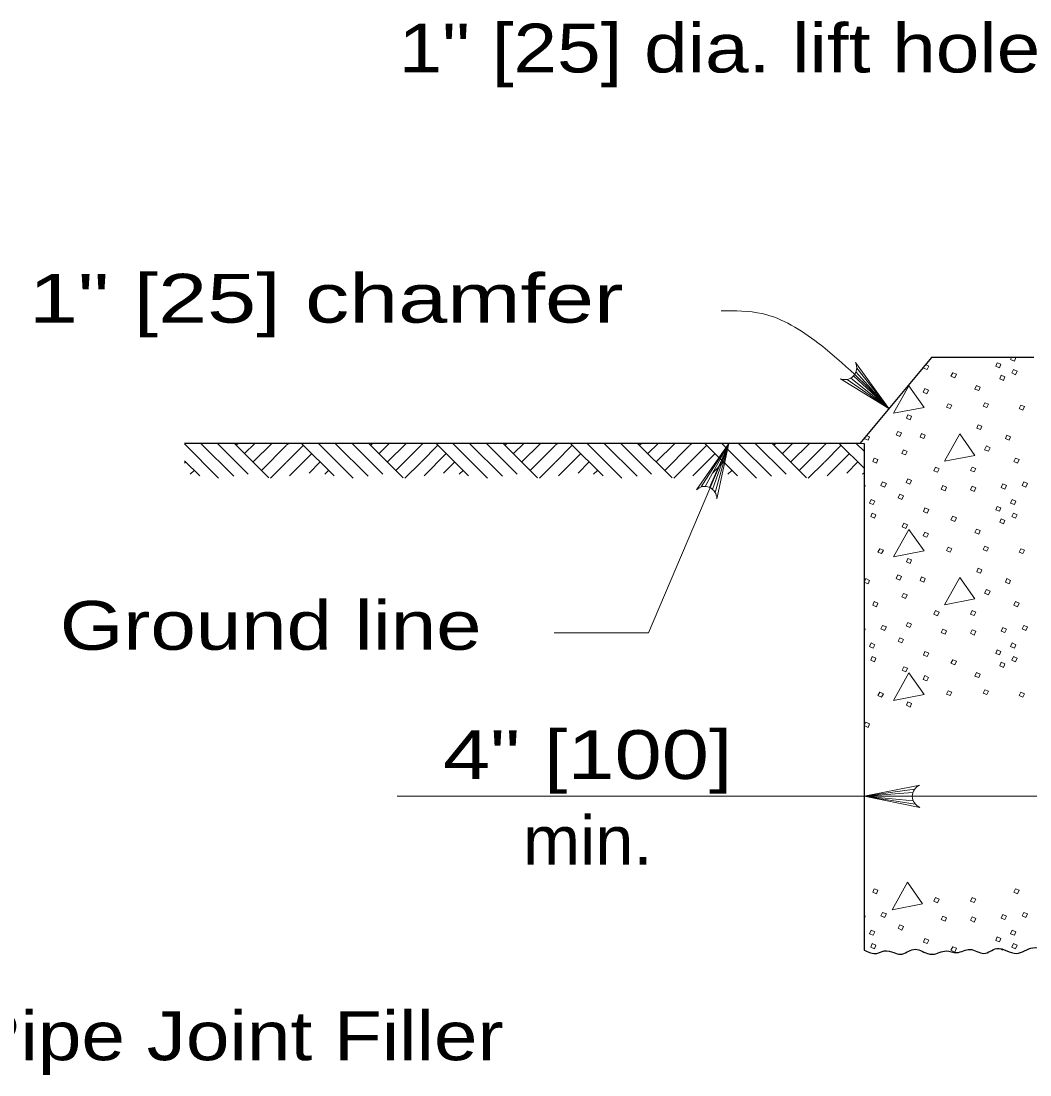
# Model space of a CAD drawing. Extents: x 1083.1 to 1117.1, y 719.4 to 741.4.
# Drawn here: x 1096.956 to 1100.181, y 731.674 to 735.044 of the extents above; entities that cross this region are included whole.
import ezdxf
from ezdxf.enums import TextEntityAlignment as Align

# ---------------------------------------------------------------- set-up
doc = ezdxf.new("R2010")
doc.units = 0
doc.header["$LTSCALE"] = 0.062
doc.layers.add('1', color=7, linetype='Continuous', lineweight=13)

msp = doc.modelspace()

# ---------------------------------------------------------------- linework, layer by layer
at = {"layer": '1'}
for p, q in [((1099.62458, 733.92192), (1099.72992, 733.80475)), ((1099.62717, 733.93383), (1099.72992, 733.80475)), ((1099.59625, 733.89767), (1099.72992, 733.80475)), ((1099.60792, 733.90217), (1099.72992, 733.80475)), ((1099.61683, 733.90933), (1099.72992, 733.80475)), ((1097.4785, 733.69167), (1097.5875, 733.58267)), ((1097.53033, 733.6935), (1097.63575, 733.58808)), ((1097.58408, 733.6935), (1097.68233, 733.59533)), ((1097.63775, 733.6935), (1097.74775, 733.58358)), ((1097.64367, 733.68758), (1097.64967, 733.6935)), ((1097.6705, 733.66075), (1097.70325, 733.6935)), ((1097.69742, 733.63392), (1097.757, 733.6935)), ((1097.72425, 733.60708), (1097.80375, 733.68658)), ((1097.80483, 733.68767), (1097.81067, 733.6935)), ((1097.80483, 733.63383), (1097.8585, 733.68758)), ((1097.85258, 733.6935), (1097.95675, 733.58942)), ((1097.90633, 733.6935), (1098.01717, 733.58267)), ((1097.96, 733.6935), (1098.0655, 733.58808)), ((1098.01375, 733.6935), (1098.11208, 733.59533)), ((1098.06742, 733.6935), (1098.1775, 733.58358)), ((1098.07342, 733.68758), (1098.07942, 733.6935)), ((1098.10025, 733.66075), (1098.133, 733.6935)), ((1098.12708, 733.63392), (1098.18675, 733.6935)), ((1098.15392, 733.60708), (1098.23342, 733.68658)), ((1098.23458, 733.68767), (1098.24042, 733.6935)), ((1098.23458, 733.63383), (1098.28825, 733.68758)), ((1098.28233, 733.6935), (1098.3865, 733.58942)), ((1098.336, 733.6935), (1098.44692, 733.58267)), ((1098.38967, 733.6935), (1098.49517, 733.58808)), ((1098.44342, 733.6935), (1098.54175, 733.59533)), ((1098.49717, 733.6935), (1098.60717, 733.58358)), ((1098.50308, 733.68758), (1098.50908, 733.6935)), ((1098.52992, 733.66075), (1098.56267, 733.6935)), ((1098.55675, 733.63392), (1098.61642, 733.6935)), ((1098.58367, 733.60708), (1098.66308, 733.68658)), ((1098.66425, 733.68767), (1098.67008, 733.6935)), ((1098.66425, 733.63383), (1098.71792, 733.68758)), ((1098.712, 733.6935), (1098.81617, 733.58942)), ((1098.76567, 733.6935), (1098.87658, 733.58267)), ((1098.81942, 733.6935), (1098.92492, 733.58808)), ((1098.87317, 733.6935), (1098.97142, 733.59533)), ((1098.92683, 733.6935), (1099.03692, 733.58358)), ((1098.93275, 733.68758), (1098.93875, 733.6935)), ((1098.95967, 733.66075), (1098.99242, 733.6935)), ((1098.9865, 733.63392), (1099.04608, 733.6935)), ((1099.01333, 733.60708), (1099.09283, 733.68658)), ((1099.09392, 733.68767), (1099.09975, 733.6935)), ((1099.09392, 733.63383), (1099.14767, 733.68758)), ((1099.13025, 733.55425), (1099.21867, 733.6935)), ((1099.14167, 733.6935), (1099.24583, 733.58942)), ((1099.14233, 733.55567), (1099.21867, 733.6935)), ((1099.15675, 733.5525), (1099.21867, 733.6935)), ((1099.16642, 733.54633), (1099.21867, 733.6935)), ((1099.17442, 733.53683), (1099.21867, 733.6935)), ((1099.19542, 733.6935), (1099.30625, 733.58267)), ((1099.24908, 733.6935), (1099.35467, 733.58808)), ((1099.30292, 733.6935), (1099.40117, 733.59533)), ((1099.35658, 733.6935), (1099.46658, 733.58358)), ((1099.3625, 733.68758), (1099.3685, 733.6935)), ((1099.38933, 733.66075), (1099.42208, 733.6935)), ((1099.41617, 733.63392), (1099.47583, 733.6935)), ((1099.443, 733.60708), (1099.5225, 733.68658)), ((1099.52367, 733.68767), (1099.5295, 733.6935)), ((1099.52367, 733.63383), (1099.57742, 733.68758)), ((1099.57142, 733.6935), (1099.65058, 733.61442)), ((1099.62508, 733.6935), (1099.65058, 733.66808)), ((1099.65058, 733.6935), (1099.63708, 733.6935)), ((1097.81425, 733.58967), (1097.88542, 733.66075)), ((1098.244, 733.58967), (1098.31508, 733.66075)), ((1098.67367, 733.58967), (1098.74475, 733.66075)), ((1099.21133, 733.67675), (1098.96125, 733.0875)), ((1099.10342, 733.58967), (1099.1745, 733.66075)), ((1099.53308, 733.58967), (1099.60417, 733.66075)), ((1097.4785, 733.638), (1097.52708, 733.58942)), ((1097.4785, 733.62992), (1097.4825, 733.63392)), ((1097.75333, 733.58233), (1097.80375, 733.63275)), ((1097.87692, 733.5985), (1097.91225, 733.63392)), ((1098.183, 733.58233), (1098.23342, 733.63275)), ((1098.30658, 733.5985), (1098.34192, 733.63392)), ((1098.61275, 733.58233), (1098.66308, 733.63275)), ((1098.73625, 733.5985), (1098.77167, 733.63392)), ((1099.0425, 733.58233), (1099.09283, 733.63275)), ((1099.166, 733.5985), (1099.20133, 733.63392)), ((1099.47217, 733.58233), (1099.5225, 733.63275)), ((1099.59567, 733.5985), (1099.631, 733.63392)), ((1097.49675, 733.5945), (1097.50942, 733.60708)), ((1097.9265, 733.5945), (1097.93908, 733.60708)), ((1098.35617, 733.5945), (1098.36875, 733.60708)), ((1098.78592, 733.5945), (1098.7985, 733.60708)), ((1099.21558, 733.5945), (1099.22817, 733.60708)), ((1099.64525, 733.5945), (1099.65058, 733.59975)), ((1098.65942, 733.0875), (1098.96125, 733.0875)), ((1099.81175, 732.58775), (1099.65058, 732.56517)), ((1099.80633, 732.57658), (1099.65058, 732.56517)), ((1098.15858, 732.56517), (1100.59642, 732.56517)), ((1099.80467, 732.56517), (1099.65058, 732.56517)), ((1099.8075, 732.55067), (1099.65058, 732.56517)), ((1099.81367, 732.54025), (1099.65058, 732.56517)), ((1100.0885, 732.07467), (1100.08892, 732.07575)), ((1100.08892, 732.07575), (1100.09458, 732.07317))]:
    msp.add_line(p, q, dxfattribs=at)
at = {"layer": '1', "lineweight": 25}
for p, q in [((1099.63708, 733.6935), (1097.4785, 733.6935)), ((1099.65058, 733.6935), (1099.65058, 732.07317))]:
    msp.add_line(p, q, dxfattribs=at)
msp.add_lwpolyline([(1100.19267, 733.96767), (1099.86592, 733.96767), (1099.63708, 733.6935)], dxfattribs=at)
at = {"layer": '1'}
for points in [[(1100.13533, 733.96767), (1100.13567, 733.9675), (1100.13092, 733.95642), (1100.119, 733.96117), (1100.12167, 733.96767)], [(1099.62342, 733.95175), (1099.72992, 733.80475), (1099.57508, 733.89958)], [(1099.84717, 733.94525), (1099.85708, 733.94058), (1099.85233, 733.9295), (1099.8405, 733.93433), (1099.84275, 733.94)], [(1099.65825, 733.71883), (1099.668, 733.71433), (1099.66325, 733.70325), (1099.65133, 733.70883), (1099.65292, 733.7125)], [(1099.1145, 733.54483), (1099.21867, 733.6935), (1099.17967, 733.51625)], [(1099.65058, 733.56025), (1099.6545, 733.5585), (1099.65058, 733.54917)], [(1099.65058, 733.10142), (1099.6545, 733.09958), (1099.65058, 733.09033)], [(1099.82858, 732.52958), (1099.65058, 732.56517), (1099.82858, 732.60075)], [(1099.65058, 732.18358), (1099.6545, 732.18175), (1099.65058, 732.1725)]]:
    msp.add_lwpolyline(points, dxfattribs=at)
for points in [[(1100.07625, 733.95092), (1100.08817, 733.94617), (1100.08342, 733.93508), (1100.0715, 733.93983)], [(1100.12775, 733.9295), (1100.13958, 733.924), (1100.13483, 733.91292), (1100.123, 733.9185)], [(1099.93383, 733.91925), (1099.94575, 733.9145), (1099.94017, 733.90267), (1099.92833, 733.90817)], [(1100.08892, 733.91133), (1100.10083, 733.90583), (1100.09608, 733.89475), (1100.08417, 733.90025)], [(1099.79383, 733.87733), (1099.74475, 733.7895), (1099.84208, 733.8085)], [(1099.84442, 733.86858), (1099.85633, 733.86308), (1099.85075, 733.852), (1099.83892, 733.85675)], [(1100.00983, 733.87808), (1100.02167, 733.87333), (1100.01692, 733.86225), (1100.00508, 733.867)], [(1099.91883, 733.82033), (1099.93067, 733.81558), (1099.92592, 733.8045), (1099.91408, 733.80925)], [(1100.03675, 733.8235), (1100.04858, 733.81875), (1100.04308, 733.80767), (1100.03117, 733.81242)], [(1100.1515, 733.81558), (1100.16333, 733.81083), (1100.15775, 733.79975), (1100.14592, 733.8045)], [(1099.79067, 733.78475), (1099.8025, 733.78), (1099.79775, 733.76817), (1099.78592, 733.77367)], [(1100.01533, 733.75308), (1100.02725, 733.74833), (1100.0225, 733.73725), (1100.01058, 733.742)], [(1099.75817, 733.73175), (1099.77008, 733.727), (1099.76533, 733.71508), (1099.75342, 733.72067)], [(1099.83417, 733.72542), (1099.846, 733.71983), (1099.84125, 733.70883), (1099.82942, 733.7135)], [(1099.95683, 733.72383), (1099.90775, 733.636), (1100.00508, 733.655)], [(1100.10717, 733.71983), (1100.119, 733.71433), (1100.11425, 733.70325), (1100.10242, 733.70883)], [(1100.0415, 733.68508), (1100.05333, 733.6795), (1100.04783, 733.66842), (1100.03592, 733.67317)], [(1099.77642, 733.67242), (1099.78825, 733.66767), (1099.78275, 733.65658), (1099.77083, 733.66133)], [(1099.683, 733.64625), (1099.69492, 733.64158), (1099.69017, 733.62967), (1099.67825, 733.63525)], [(1099.8785, 733.61783), (1099.89033, 733.61225), (1099.88558, 733.60117), (1099.87375, 733.60592)], [(1099.99633, 733.61783), (1100.00825, 733.61308), (1100.00267, 733.602), (1099.99083, 733.60675)], [(1100.13408, 733.64625), (1100.14592, 733.64158), (1100.14117, 733.62967), (1100.12933, 733.63525)], [(1099.70992, 733.57033), (1099.72175, 733.56558), (1099.71625, 733.55375), (1099.70442, 733.55925)], [(1099.79067, 733.57983), (1099.8025, 733.57425), (1099.79692, 733.56325), (1099.78508, 733.56875)], [(1099.90217, 733.5585), (1099.91408, 733.55292), (1099.90933, 733.54183), (1099.89742, 733.54742)], [(1099.99633, 733.55608), (1100.00825, 733.55133), (1100.00267, 733.5395), (1099.99083, 733.545)], [(1100.09367, 733.564), (1100.10558, 733.5585), (1100.10083, 733.54742), (1100.08892, 733.55217)], [(1100.16092, 733.57033), (1100.17283, 733.56558), (1100.16725, 733.55375), (1100.15542, 733.55925)], [(1099.7645, 733.53075), (1099.77642, 733.52525), (1099.77167, 733.51417), (1099.75975, 733.51967)], [(1099.67275, 733.51417), (1099.68458, 733.50858), (1099.67983, 733.49758), (1099.668, 733.50225)], [(1099.84525, 733.48725), (1099.85708, 733.48175), (1099.85233, 733.47067), (1099.8405, 733.47542)], [(1100.07625, 733.492), (1100.08817, 733.48725), (1100.08342, 733.47617), (1100.0715, 733.48092)], [(1100.12375, 733.51417), (1100.13567, 733.50858), (1100.13092, 733.49758), (1100.119, 733.50225)], [(1099.67667, 733.47067), (1099.68858, 733.46508), (1099.68383, 733.454), (1099.67192, 733.45958)], [(1099.93383, 733.46033), (1099.94575, 733.45558), (1099.94017, 733.44375), (1099.92833, 733.44925)], [(1100.08892, 733.45242), (1100.10083, 733.44692), (1100.09608, 733.43583), (1100.08417, 733.44133)], [(1100.12775, 733.47067), (1100.13958, 733.46508), (1100.13483, 733.454), (1100.123, 733.45958)], [(1099.79383, 733.41842), (1099.74475, 733.33058), (1099.84208, 733.34958)], [(1099.77717, 733.43817), (1099.78908, 733.43342), (1099.78433, 733.42158), (1099.77242, 733.42708)], [(1100.00983, 733.41925), (1100.02167, 733.4145), (1100.01692, 733.40342), (1100.00508, 733.40817)], [(1099.84442, 733.40975), (1099.85633, 733.40417), (1099.85075, 733.39308), (1099.83892, 733.39783)], [(1099.70042, 733.35667), (1099.71225, 733.35192), (1099.70675, 733.34092), (1099.69492, 733.34567)], [(1099.91883, 733.36142), (1099.93067, 733.35667), (1099.92592, 733.34567), (1099.91408, 733.35042)], [(1100.03675, 733.36458), (1100.04858, 733.35983), (1100.04308, 733.34883), (1100.03117, 733.35358)], [(1100.1515, 733.35667), (1100.16333, 733.35192), (1100.15775, 733.34092), (1100.14592, 733.34567)], [(1099.79067, 733.32583), (1099.8025, 733.32108), (1099.79775, 733.30925), (1099.78592, 733.31475)], [(1100.01533, 733.29417), (1100.02725, 733.28942), (1100.0225, 733.27833), (1100.01058, 733.28308)], [(1099.65608, 733.261), (1099.668, 733.25542), (1099.66325, 733.24433), (1099.65133, 733.24992)], [(1099.75817, 733.27283), (1099.77008, 733.26808), (1099.76533, 733.25625), (1099.75342, 733.26175)], [(1099.83417, 733.2665), (1099.846, 733.261), (1099.84125, 733.24992), (1099.82942, 733.25467)], [(1099.95683, 733.26492), (1099.90775, 733.17708), (1100.00508, 733.19608)], [(1100.10717, 733.261), (1100.119, 733.25542), (1100.11425, 733.24433), (1100.10242, 733.24992)], [(1099.77642, 733.2135), (1099.78825, 733.20875), (1099.78275, 733.19767), (1099.77083, 733.20242)], [(1100.0415, 733.22617), (1100.05333, 733.22058), (1100.04783, 733.2095), (1100.03592, 733.21425)], [(1099.683, 733.18742), (1099.69492, 733.18267), (1099.69017, 733.17075), (1099.67825, 733.17633)], [(1100.13408, 733.18742), (1100.14592, 733.18267), (1100.14117, 733.17075), (1100.12933, 733.17633)], [(1099.8785, 733.15892), (1099.89033, 733.15333), (1099.88558, 733.14225), (1099.87375, 733.147)], [(1099.99633, 733.15892), (1100.00825, 733.15417), (1100.00267, 733.14308), (1099.99083, 733.14783)], [(1099.79067, 733.12092), (1099.8025, 733.11542), (1099.79692, 733.10433), (1099.78508, 733.10983)], [(1099.70992, 733.11142), (1099.72175, 733.10667), (1099.71625, 733.09483), (1099.70442, 733.10033)], [(1099.90217, 733.09958), (1099.91408, 733.094), (1099.90933, 733.08292), (1099.89742, 733.0885)], [(1099.99633, 733.09717), (1100.00825, 733.09242), (1100.00267, 733.08058), (1099.99083, 733.08608)], [(1100.09367, 733.10508), (1100.10558, 733.09958), (1100.10083, 733.0885), (1100.08892, 733.09325)], [(1100.16092, 733.11142), (1100.17283, 733.10667), (1100.16725, 733.09483), (1100.15542, 733.10033)], [(1099.67275, 733.05525), (1099.68458, 733.04975), (1099.67983, 733.03867), (1099.668, 733.04342)], [(1099.7645, 733.07183), (1099.77642, 733.06633), (1099.77167, 733.05525), (1099.75975, 733.06083)], [(1100.12375, 733.05525), (1100.13567, 733.04975), (1100.13092, 733.03867), (1100.119, 733.04342)], [(1099.67667, 733.01175), (1099.68858, 733.00617), (1099.68383, 732.99508), (1099.67192, 733.00067)], [(1099.84525, 733.02833), (1099.85708, 733.02283), (1099.85233, 733.01175), (1099.8405, 733.0165)], [(1100.07625, 733.03308), (1100.08817, 733.02833), (1100.08342, 733.01725), (1100.0715, 733.022)], [(1100.12775, 733.01175), (1100.13958, 733.00617), (1100.13483, 732.99508), (1100.123, 733.00067)], [(1099.77717, 732.97933), (1099.78908, 732.97458), (1099.78433, 732.96267), (1099.77242, 732.96825)], [(1099.93383, 733.00142), (1099.94575, 732.99667), (1099.94017, 732.98483), (1099.92833, 732.99033)], [(1100.08892, 732.9935), (1100.10083, 732.988), (1100.09608, 732.97692), (1100.08417, 732.9825)], [(1099.79383, 732.9595), (1099.74475, 732.87167), (1099.84208, 732.89067)], [(1099.84442, 732.95083), (1099.85633, 732.94525), (1099.85075, 732.93417), (1099.83892, 732.93892)], [(1100.00983, 732.96033), (1100.02167, 732.95558), (1100.01692, 732.9445), (1100.00508, 732.94925)], [(1099.70042, 732.89783), (1099.71225, 732.89308), (1099.70675, 732.882), (1099.69492, 732.88675)], [(1099.91883, 732.90258), (1099.93067, 732.89783), (1099.92592, 732.88675), (1099.91408, 732.8915)], [(1100.03675, 732.90575), (1100.04858, 732.901), (1100.04308, 732.88992), (1100.03117, 732.89467)], [(1100.1515, 732.89783), (1100.16333, 732.89308), (1100.15775, 732.882), (1100.14592, 732.88675)], [(1099.79067, 732.86692), (1099.8025, 732.86217), (1099.79775, 732.85033), (1099.78592, 732.85583)], [(1099.65608, 732.80208), (1099.668, 732.7965), (1099.66325, 732.78542), (1099.65133, 732.791)], [(1099.683, 732.26958), (1099.69492, 732.26483), (1099.69017, 732.253), (1099.67825, 732.2585)], [(1099.78892, 732.29), (1099.73983, 732.20217), (1099.83717, 732.22117)], [(1100.13408, 732.26958), (1100.14592, 732.26483), (1100.14117, 732.253), (1100.12933, 732.2585)], [(1099.8785, 732.24108), (1099.89033, 732.23558), (1099.88558, 732.2245), (1099.87375, 732.22925)], [(1099.99633, 732.24108), (1100.00825, 732.23633), (1100.00267, 732.22525), (1099.99083, 732.23)], [(1099.70992, 732.19358), (1099.72175, 732.18892), (1099.71625, 732.177), (1099.70442, 732.18258)], [(1099.90217, 732.18175), (1099.91408, 732.17625), (1099.90933, 732.16517), (1099.89742, 732.17067)], [(1099.99633, 732.17942), (1100.00825, 732.17467), (1100.00267, 732.16275), (1099.99083, 732.16833)], [(1100.09367, 732.18733), (1100.10558, 732.18175), (1100.10083, 732.17067), (1100.08892, 732.17542)], [(1100.16092, 732.19358), (1100.17283, 732.18892), (1100.16725, 732.177), (1100.15542, 732.18258)], [(1099.67275, 732.13742), (1099.68458, 732.13192), (1099.67983, 732.12083), (1099.668, 732.12558)], [(1099.7645, 732.15408), (1099.77642, 732.1485), (1099.77167, 732.13742), (1099.75975, 732.143)], [(1100.12375, 732.13742), (1100.13567, 732.13192), (1100.13092, 732.12083), (1100.119, 732.12558)], [(1099.84525, 732.11058), (1099.85708, 732.105), (1099.85233, 732.09392), (1099.8405, 732.09867)], [(1100.07625, 732.11533), (1100.08817, 732.11058), (1100.08342, 732.0995), (1100.0715, 732.10425)], [(1099.67667, 732.09392), (1099.68858, 732.08842), (1099.68383, 732.07733), (1099.67192, 732.08283)], [(1099.93383, 732.08367), (1099.94575, 732.07892), (1099.94017, 732.067), (1099.92833, 732.07258)], [(1100.12775, 732.09392), (1100.13958, 732.08842), (1100.13483, 732.07733), (1100.123, 732.08283)]]:
    msp.add_lwpolyline(points, close=True, dxfattribs=at)
for centre, major_axis, start_param, end_param in [((1099.58865, 733.93549), (-0.03843, 0), 1.2096381, 3.5802512), ((1099.14124, 733.51732), (0.03843, 0), 6.2546346, 8.6252477), ((1099.84306, 732.56518), (-0.03843, 0), 5.0978942, 7.4685073)]:
    msp.add_ellipse(centre, major_axis=major_axis, ratio=0.999895, start_param=start_param, end_param=end_param, dxfattribs=at)
msp.add_spline([(1099.19325, 734.11675), (1099.32483, 734.10817), (1099.503, 734.01475), (1099.72992, 733.80475)], degree=3, dxfattribs=at)
at = {"layer": '1', "lineweight": 25}
msp.add_spline([(1099.65058, 732.07317), (1099.69125, 732.0625), (1099.71475, 732.07033), (1099.74608, 732.06517), (1099.767, 732.05992), (1099.80875, 732.07558), (1099.85317, 732.0625), (1099.86883, 732.05992), (1099.91317, 732.07033), (1099.94717, 732.06517), (1099.98892, 732.07558), (1100.03333, 732.0625), (1100.07508, 732.07817), (1100.13775, 732.0625), (1100.19, 732.08083), (1100.24742, 732.073), (1100.31275, 732.09383), (1100.38325, 732.07033), (1100.43033, 732.08867), (1100.50342, 732.08083), (1100.53733, 732.09383), (1100.5965, 732.07317)], degree=3, dxfattribs=at)

# ---------------------------------------------------------------- texts
at = {"layer": '1'}
for s, width, p in [('1" [25] dia. lift hole', 1.2, (1098.16275, 734.87942)), ('1" [25] chamfer', 1.35, (1096.98108, 734.07942)), ('Ground line', 1.25, (1097.07983, 733.0335)), ('Pipe Joint Filler', 1.2, (1096.78708, 731.72108))]:
    msp.add_text(s, height=0.156, dxfattribs=dict(at, width=width)).set_placement(p)
for s, width, p in [('4" [100]', 1.3, (1098.76717, 732.62033)), ('min.', 1.05, (1098.76717, 732.34633))]:
    msp.add_text(s, height=0.156, dxfattribs=dict(at, width=width)).set_placement(p, align=Align.CENTER)

doc.saveas('drawing.dxf')
